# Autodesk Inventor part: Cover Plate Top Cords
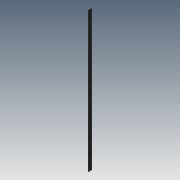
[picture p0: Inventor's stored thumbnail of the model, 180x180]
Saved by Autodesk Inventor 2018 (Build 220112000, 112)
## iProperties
Created: 2018-02
Part Number: Cover Plate Top Cords
Material: Steel, Mild
Document SubType Name: Modeling
Designer: STK
Density: 7.85 g/cm^3
Appearance: Rubber - Black
Author: STK
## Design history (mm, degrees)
sketch "Sketch1"
  geometry: L1 (-7920.037, 196.85)-(7920.037, 196.85); L2 (7920.037, 196.85)-(7920.037, -196.85); L3 (7920.037, -196.85)-(-7920.037, -196.85); L4 (-7920.037, -196.85)-(-7920.037, 196.85); L5 (-7920.037, 196.85)-(7920.037, -196.85); L6 (7920.037, 196.85)-(-7920.037, -196.85); 1 further point
  constraints: 12 end point, 2 midpoint, 2 parallel, 1 horizontal, 1 perpendicular
  dimensions: "d0" = 15840.075 distance of L2.end L3.end; "d1" = 393.7 distance of L1.end L2.end
extrude "Extrusion1" new body sketch "Sketch1" distance "d2" = 6.35; taper "d3" = 0 deg
body "Solid1"
